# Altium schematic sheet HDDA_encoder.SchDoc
size Tabloid; Organization: CMU Robotics Institute; Address1: Suite 780; Address2: 5001 Baum Blvd; Address3: Pittsburgh, PA 15213; Address4: USA
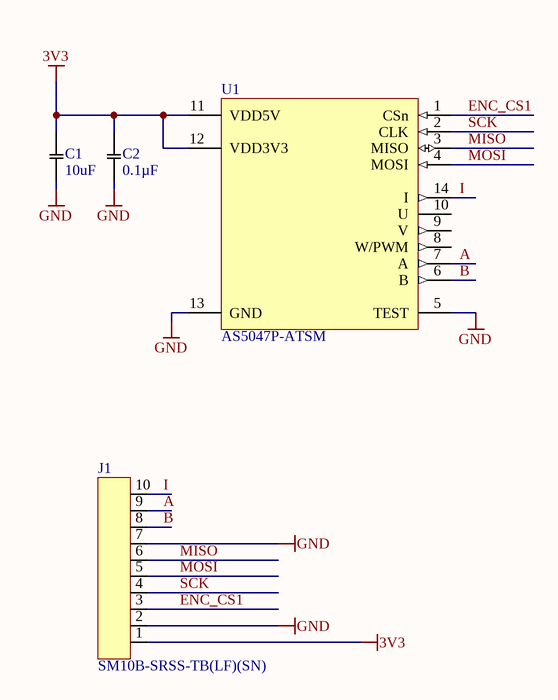
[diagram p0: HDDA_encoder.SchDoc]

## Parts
C1  10uF  [C0603]
C2  0.1µF  [C0402]
J1  SM10B-SRSS-TB(LF)(SN)  [SM10B-SRSS-TB]
U1  AS5047P-ATSM  [AS5047X]

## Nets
3V3: C1.1 C2.1 J1.1 U1.11(VDD5V) U1.12(VDD3V3)
GND: C1.2 C2.2 J1.2 J1.7 U1.5(TEST) U1.13(GND)
A: J1.9 U1.7(A)
B: J1.8 U1.6(B)
ENC_CS1: J1.3 U1.1(CSn)
I: J1.10 U1.14(I)
MISO: J1.6 U1.3(MISO)
MOSI: J1.5 U1.4(MOSI)
SCK: J1.4 U1.2(CLK)

Not connected (* = marked no-connect by the designer): U1 8(W/PWM) 9(V) 10(U)

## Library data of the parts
C1 = C1608X5R1A106K080AC: CAP CER 10UF 10V 10% X5R 0603; Manufacturer: TDK Corporation
C2 = C1005X7R1H104K050BB: CAP CER 0.1UF 50V 10% X7R 0402; Manufacturer: TDK Corporation
J1 = SM10B-SRSS-TB(LF)(SN): CONN HEADER SH 10POS SIDE 1MM TIN; Manufacturer: JST Sales America Inc; Connector Type: Header, Shrouded; Number of Positions: 10; Number of Positions Loaded: All; Pitch: 0.039" (1.00mm)
U1 = AS5047P-ATSM: IC ENCODER ROTARY 14TSSOP; Manufacturer: ams; Sensing Range: 35mT ~ 70mT; Voltage - Supply: 4.5 V ~ 5.5 V; Current - Supply: 15mA; Current - Output (Max): 4mA; Output Type: SPI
